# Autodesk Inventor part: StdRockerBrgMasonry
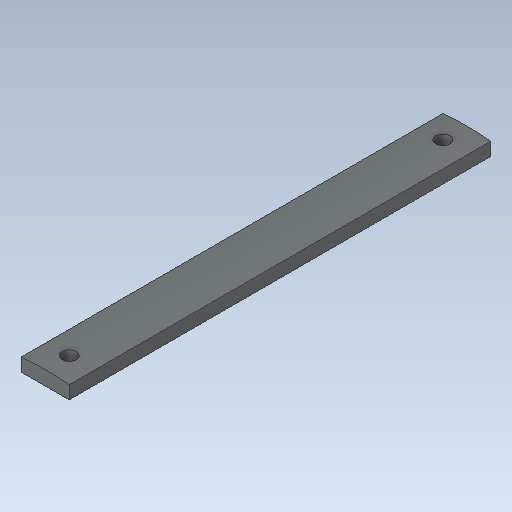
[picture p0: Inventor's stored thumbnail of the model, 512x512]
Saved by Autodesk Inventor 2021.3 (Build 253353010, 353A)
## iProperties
Created: 2019-05
Part Number: StdRockerBrgMasonry
Material: Steel, Galvanized
Document SubType Name: Modeling
Designer: u1426
Density: 7.85 g/cm^3
Appearance: Galvanized
BoltDiameter: 1.250 in
MasonryThickness: 1.500 in
MasonryEdgeDist: 2.500 in
MasonryLength: 44.000 in
MasonryWidth: 5.000 in
d81: 2.500 in
d71: 1.500 in
Author: u1426
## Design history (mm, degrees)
sketch "MasonryPL"
  geometry: L1 (63.5, 0)-(63.5, 34.784); L2 (63.5, 0)-(-63.5, 0); L3 (-63.5, 0)-(-63.5, 34.784); A1 r 609.6 centre (0, -571.5) between (63.5, 34.784) and (-63.5, 34.784); 1 further point
  constraints: 6 end point, 2 point on circle, 2 vertical, 1 centre point, 1 horizontal, 1 horizontal alignment, 1 midpoint, 2 other
  dimensions: "d84" = 609.6 radius of A1
extrude "MasonryPlate" new body sketch "MasonryPL" taper "d70" = 0 deg
sketch "MasonryPLHole"
  geometry: L1 (127, 0)-(0, 0) reference; L2 (127, -1117.6)-(127, 0) reference; L3 (0, -1117.6)-(0, 0) reference; L4 (0, -1117.6)-(127, -1117.6) reference; 3 further points
  constraints: 2 other
  dimensions: "d79" = 63.5 distance from line of point (63.5, -63.5) L2 (derived); "d80" = 63.5 distance from line of point (63.5, -1054.1) L3 (= d79)
hole "MasonryHoles" sketch "MasonryPLHole" at (63.5, -63.5), (63.5, -1054.1) stored, may be unused: countersink angle "d75" = 82 deg, drill point angle "d77" = 118 deg; dims "d72" = 19.05, "d73" = 9.525, "d74" = 6.35, "d76" = 25.4
body "Solid4"
